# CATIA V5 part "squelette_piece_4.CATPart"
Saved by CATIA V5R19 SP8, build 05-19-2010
Part number: squelette_piece_4
Publications: "Point.6", "Point.5", "Droite.3", "Point.4", "Point.3", "Droite.2", "Point.2", "Point.1", "Droite.1"
Bounding box of the stored display mesh (mm): x -25 to 45, y 0 to 381, z -500 to -500
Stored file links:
  G:\EU_thinkMotion\CFAO_2010\SIL_groupe1\SIL_groupe1\A reprendre\lalpha\lalpha\Alpha.mécanisme\squelette_piece_4.CATPart
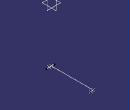
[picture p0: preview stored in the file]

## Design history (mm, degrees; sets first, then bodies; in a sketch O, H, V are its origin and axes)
Set1
  Line1: type PtPt, FirstPoint Point1, SecondPoint Point2
  Point1: stored without definition
  Point2: stored without definition
  Line2: type PtPt, FirstPoint Point3, SecondPoint Point4
  Point3: stored without definition
  Point4: stored without definition
  Line3: type PtPt, FirstPoint Point5, SecondPoint Point6, Start 25, End 25
  Point5: stored without definition
  Point6: stored without definition
Body1 (main body)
